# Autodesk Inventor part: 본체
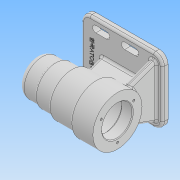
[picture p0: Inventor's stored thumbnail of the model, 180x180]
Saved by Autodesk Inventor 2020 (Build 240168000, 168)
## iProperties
Created: 2021-10
Part Number: 본체
Material: 일반
Document SubType Name: Modeling
Designer: user
Density: 1 g/cm^3
Appearance: 기본값
Author: user
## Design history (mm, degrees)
sketch "스케치1"
  geometry: L1 (-56, 0)-(56, 0); L2 (-56, 0)-(-56, 7.5); L3 (-53, 10.5)-(-53, 10.5); L4 (-53, 10.5)-(-53, 15.7); L5 (-52.7, 16)-(-49, 16); L6 (-49, 16)-(-49, 17.2); L7 (-48.7, 17.5)-(-31, 17.5); L8 (-31, 17.5)-(-31, 21); L9 (-31, 21)-(-19, 21); L10 (-19, 21)-(-19, 21); L11 (-16, 24)-(32, 24); L12 (35, 21)-(35, 21); L13 (35, 21)-(50, 21); L14 (-56, 0)-(-62, 0); L15 (-62, 0)-(-62, 25); L16 (-62, 25)-(-38, 25); L17 (-38, 25)-(-38, 27); L18 (-38, 27)-(-16, 27); L19 (-16, 27)-(-16, 27); L20 (-13, 30)-(18, 30); L21 (18, 30)-(18, 31); L22 (21, 34)-(50, 34); L23 (50, 34)-(50, 21); A1 r 0.3 centre (-52.7, 15.7) between (-52.7, 16) and (-53, 15.7); A2 r 0.3 centre (-48.7, 17.2) between (-48.7, 17.5) and (-49, 17.2); A3 r 3 centre (-53, 7.5) between (-53, 10.5) and (-56, 7.5); A4 r 3 centre (-16, 21) between (-16, 24) and (-19, 21); A5 r 3 centre (32, 21) between (35, 21) and (32, 24); A6 r 3 centre (21, 31) between (21, 34) and (18, 31); A7 r 3 centre (-13, 27) between (-13, 30) and (-16, 27); 11 further points
  constraints: 46 end point, 17 perpendicular, 14 point on circle, 14 tangent, 10 point on line, 7 centre point, 4 vertical, 3 equal radius, 2 coincident, 2 horizontal, 1 midpoint
  dimensions: "d3" = 112 distance of L1.start L1.end; "d4" = 10.5 distance of L1.start point (-56, 10.5); "d5" = 3 distance of point (-56, 10.5) L3.end; "d6" = 4 distance of point (-53, 16) L5.end; "d7" = 18 distance of point (-49, 17.5) L7.end; "d8" = 12 distance of L8.end L9.end; "d9" = 32 diameter of L5 L1; "d10" = 35 diameter of L7 L1; "d11" = 42 diameter of L9 L1; "d12" = 54 distance of point (-19, 24) point (35, 24); "d13" = 48 diameter of L11 L1; "d14" = 15 distance of L12.end L13.end; "d15" = 42 diameter of L13 L1; "d16" = 0.3 radius of A1; "d17" = 3 radius of A3; "d18" = 3 radius of A4 (derived); "d19" = 112 distance between parallel lines of L23 L15; "d20" = 24 distance of L15.end L16.end; "d21" = 46 distance between parallel lines of L19 L15; "d22" = 80 distance between parallel lines of L21 L15; "d24" = 50 diameter of L16 L1; "d25" = 54 diameter of L18 L1; "d26" = 60 diameter of L20 L1; "d27" = 68 diameter of L22 L1; "d28" = 3 radius of A6 (derived)
revolve "회전1" sketch "스케치1" stored, may be unused: angle "d29" = 90 deg
fillet "모깎기1" dims "d30" = 8
fillet "모깎기2" dims "d31" = 3
node "작업 평면1"
sketch "스케치2"
  geometry: L1 (-50, 45)-(38, 45); L2 (50, 33)-(50, -33); L3 (38, -45)-(-50, -45); L4 (-62, -33)-(-62, 33); L5 (-62, 45)-(50, -45); L6 (50, 45)-(-62, -45); L7 (50, -34)-(50, 34) reference; A1 r 12 centre (-50, 33) between (-50, 45) and (-62, 33); A2 r 12 centre (38, 33) between (50, 33) and (38, 45); A3 r 12 centre (38, -33) between (38, -45) and (50, -33); A4 r 12 centre (-50, -33) between (-62, -33) and (-50, -45); 3 further points
  constraints: 12 end point, 8 point on circle, 8 point on line, 8 tangent, 4 centre point, 3 equal radius, 3 midpoint, 2 parallel, 1 collinear, 1 horizontal, 1 horizontal alignment, 1 perpendicular
  dimensions: "d33" = 112 distance of L5.end L6.end; "d34" = 90 distance of L6.start L5.end; "d35" = 12 radius of A1
extrude "돌출1" join sketch "스케치2" distance "d36" = 8; taper "d37" = 0 deg
sketch "스케치3"
  geometry: L1 (50, -33)-(50, 33) reference; L2 (-35, 4)-(42, 4); L3 (42, 4)-(42, -4); L4 (42, -4)-(-35, -4); L5 (-35, -4)-(-35, 4); L6 (-35, 4)-(42, -4); L7 (42, 4)-(-35, -4); 3 further points
  constraints: 12 end point, 3 midpoint, 2 parallel, 1 horizontal, 1 horizontal alignment, 1 perpendicular
  dimensions: "d38" = 77 distance of L3.end L4.end; "d39" = 8 distance of L2.end L3.end; "d40" = 8 distance between parallel lines of L1 L3
extrude "돌출2" join sketch "스케치3" stored distance "d41" = 8; taper "d42" = 0 deg
sketch "스케치4"
  geometry: L1 (0, 0)-(-28.236, 0) reference; L2 (0, 8)-(-28.236, 8) reference; L3 (-37.342, -19.409)-(0, -33); L4 (-37.342, 27.409)-(0, 41); L5 (0, -29)-(0, -41) reference; L6 (0, 49)-(0, 37) reference; L7 (8, -40.314)-(0, -40.314) reference; L8 (0, -40.314)-(0, 0) reference; L9 (0, 0)-(-28.236, 0) reference; L10 (-28.236, 8)-(0, 8) reference; L11 (0, 8)-(0, 48.314) reference; L12 (0, 48.314)-(8, 48.314) reference; L13 (8, 48.314)-(8, -40.314) reference; L14 (0, 0)-(0, 8) reference; C1 r 21 at (-62, 4) reference; A1 r 34 centre (-62, 4) between (-28.236, 8) and (-28.236, 0) reference; A2 r 34 centre (-62, 4) between (-28.236, 0) and (-28.236, 8) reference; A3 r 34 centre (-62, 4) between (-28.236, 8) and (-28.236, 0) reference
  constraints: 4 end point, 2 point on circle, 2 point on line
  dimensions: "d43" = 8 distance of L5.end L3.end; "d44" = 8 distance of L6.start L4.end; "d45" = 110 deg angle of L3 L8; "d46" = 110 deg angle of L11 L4
extrude "돌출3" join sketch "스케치4" distance "d47" = 8; taper "d48" = 0 deg
feature "면 기울기1" dims angle "d49" = 15 deg
sketch "스케치5"
  geometry: L1 (-62, 33)-(-62, -33) reference; L2 (-50, -45)-(38, -45) reference; L3 (-42, -33)-(-27, -33); L4 (-42, -37.5)-(-27, -37.5); L5 (-27, -28.5)-(-42, -28.5); L6 (42, -37)-(34, -37) reference; L7 (34, -37)-(34, -4) reference; L8 (34, -4)-(-35, -4) reference; L9 (-35, -4)-(-35, 4) reference; L10 (-35, 4)-(34, 4) reference; L11 (34, 4)-(34, 37) reference; L12 (34, 37)-(42, 37) reference; L13 (42, 37)-(42, -37) reference; L14 (38, -45)-(-50, -45) reference; L15 (-62, -33)-(-62, 33) reference; L16 (-50, 45)-(38, 45) reference; L17 (50, 33)-(50, -33) reference; L18 (-2, -33)-(13, -33); L19 (-2, -37.5)-(13, -37.5); L20 (13, -28.5)-(-2, -28.5); L21 (-42, 33)-(-27, 33); L22 (-42, 28.5)-(-27, 28.5); L23 (-27, 37.5)-(-42, 37.5); L24 (-2, 33)-(13, 33); L25 (-2, 28.5)-(13, 28.5); L26 (13, 37.5)-(-2, 37.5); A1 r 4.5 centre (-42, -33) between (-42, -28.5) and (-42, -37.5); A2 r 4.5 centre (-27, -33) between (-27, -37.5) and (-27, -28.5); A3 r 12 centre (-50, -33) between (-62, -33) and (-50, -45) reference; A4 r 12 centre (-50, 33) between (-50, 45) and (-62, 33) reference; A5 r 12 centre (38, 33) between (50, 33) and (38, 45) reference; A6 r 12 centre (38, -33) between (38, -45) and (50, -33) reference; A7 r 4.5 centre (-2, -33) between (-2, -28.5) and (-2, -37.5); A8 r 4.5 centre (13, -33) between (13, -37.5) and (13, -28.5); A9 r 4.5 centre (-42, 33) between (-42, 37.5) and (-42, 28.5); A10 r 4.5 centre (-27, 33) between (-27, 28.5) and (-27, 37.5); A11 r 4.5 centre (-2, 33) between (-2, 37.5) and (-2, 28.5); A12 r 4.5 centre (13, 33) between (13, 28.5) and (13, 37.5); 5 further points
  constraints: 32 end point, 16 point on circle, 16 tangent, 8 centre point, 6 parallel, 4 midpoint, 2 point on line, 1 horizontal
  dimensions: "d50" = 15 distance of L3.start L3.end; "d51" = 9 diameter of A2; "d54" = 20 distance from line of L15 L3.start; "d55" = 33 vertical distance of point (0, 0) point (-34.5, -33); "d56" = 15 distance of L18.start L18.end; "d57" = 9 diameter of A8; "d58" = 15 distance of L21.start L21.end; "d59" = 9 diameter of A10; "d60" = 15 distance of L24.start L24.end; "d61" = 9 diameter of A12; "d62" = 60 distance from line of L1 L18.start; "d63" = 33 vertical distance of point (0, 0) point (5.5, -33); "d64" = 20 distance of L1.start L21.start; "d65" = 33 vertical distance of point (0, 0) point (-34.5, 33); "d66" = 60 distance from line of L1 L24.start
extrude "돌출4" cut sketch "스케치5" distance "d67" = 300; taper "d68" = 0 deg
sketch "스케치6"
  geometry: C1 r 34 at (0, 0) reference; 1 further point
  constraints: 1 vertical alignment
  dimensions: "d69" = 26 distance of point (0, -26) C1.centre
hole "구멍1" sketch "스케치6" at (0, -26) diameter "d70" = 3.242; stored, may be unused: countersink angle "d74" = 90 deg, drill point angle "d76" = 118 deg; dims "d71" = 8, "d72" = 4, "d73" = 2, "d75" = 11
fillet "모깎기3" dims "d80" = 3
fillet "모깎기4" dims "d81" = 3
fillet "모깎기5" dims "d82" = 3
chamfer "모따기1" distance "d83" = 1; stored, may be unused: second distance "d84" = 2, angle "d85" = 45 deg
sketch "스케치7"
  geometry: L1 (-59, -33)-(-59, 33) reference; 2 further points
  constraints: 1 horizontal alignment, 1 other
  dimensions: "d86" = 12 distance from line of L1 point (-47, 0)
feature "엠보싱1" sketch "스케치7" dims "d3" = 112, "d4" = 10.5, "d5" = 3, "d6" = 4, "d7" = 18, "d8" = 12, "d9" = 32, "d10" = 35, "d11" = 42, "d12" = 54, "d13" = 48, "d14" = 15, "d15" = 42, "d16" = 0.3, "d17" = 3, "d18" = 3 (derived), "d19" = 112, "d20" = 24, "d21" = 46, "d22" = 80, "d24" = 50, "d25" = 54, "d26" = 60, "d27" = 68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
fillet "모깎기6" dims "d89" = 0.3
node "솔리드1"
pattern_circular "원형 패턴1" dims angle "d78" = 360 deg
node "절단 모서리 투영1"
node "절단 모서리 투영2"
feature "A9D066F2-1C7D-4E18-AEED-F7BC21143FA4" dims "d70" = 3.242, "d71" = 8, "d72" = 4, "d73" = 2, "d74" = 90 deg, "d75" = 11, "d76" = 118 deg
